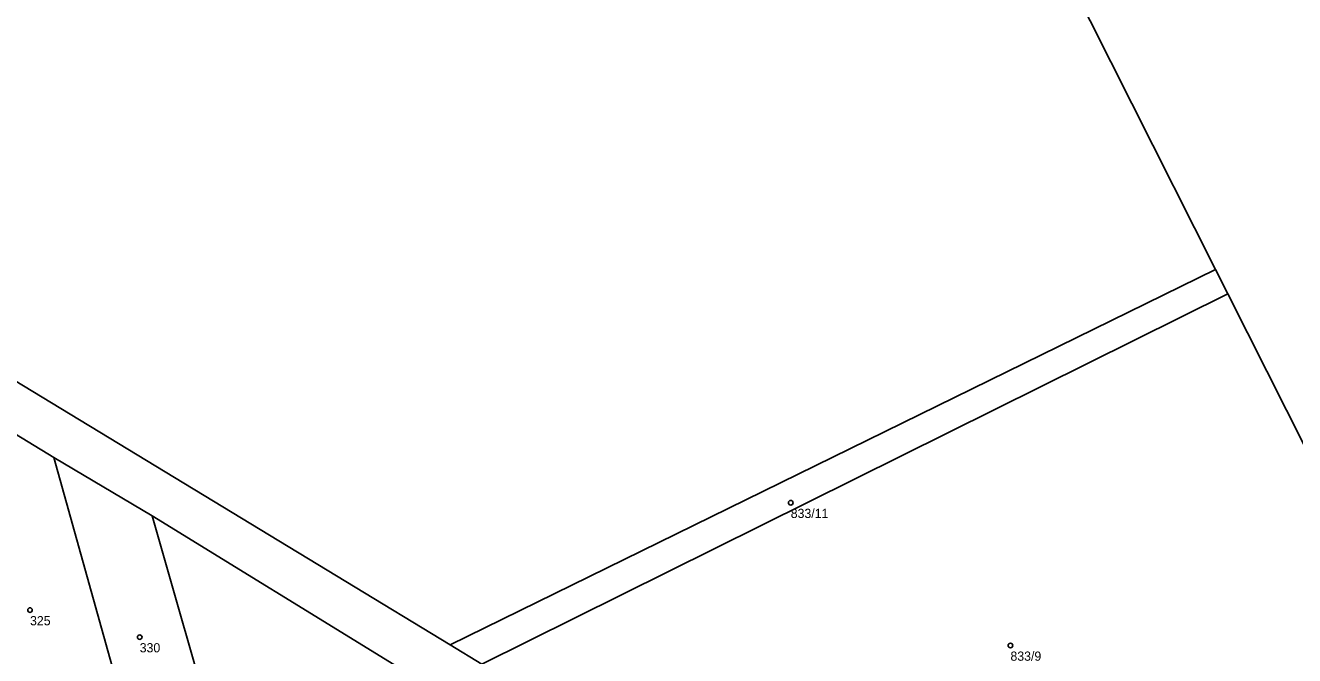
# Model space of a CAD drawing. Extents: x -550098 to -546083, y -1127254 to -1124489.
# Drawn here: x -547295.2 to -547157.4, y -1125565.9 to -1125497.4 of the extents above; entities that cross this region are included whole.
import ezdxf

# ---------------------------------------------------------------- set-up
doc = ezdxf.new("R2010")
doc.units = 0
doc.layers.add('Definiční body', color=7, linetype='Continuous')
doc.layers.add('Polygon parcely', color=7, linetype='Continuous')

msp = doc.modelspace()

# ---------------------------------------------------------------- linework, layer by layer
at = {"layer": 'Definiční body'}
for centre in [(-547212.11, -1125549.23994), (-547294.72, -1125560.89994), (-547282.81, -1125563.83994), (-547188.25, -1125564.74994)]:
    msp.add_circle(centre, 0.25, dxfattribs=at)
at = {"layer": 'Polygon parcely'}
for points in [[(-547165.99, -1125523.88), (-547164.64, -1125526.55), (-547143.41, -1125568.71), (-547117.13, -1125555.75), (-547050.4, -1125523.01), (-547167.11, -1125292.24), (-547252.28, -1125352.54)], [(-547165.99, -1125523.88), (-547252.28, -1125352.54), (-547253.34, -1125353.29), (-547407.05, -1125462.23), (-547406.74, -1125468.91), (-547249.09, -1125564.68)], [(-547245.67, -1125566.76), (-547249.09, -1125564.68), (-547406.74, -1125468.91), (-547411.12, -1125466.23), (-547419.21, -1125474.16), (-547411.31, -1125471.93), (-547407.3, -1125474.3), (-547391.7, -1125483.88), (-547369.07, -1125497.57), (-547353.56, -1125506.98), (-547338.11, -1125516.36), (-547322.81, -1125525.58), (-547307.78, -1125534.79), (-547292.14, -1125544.32), (-547281.45, -1125550.65), (-547255.23, -1125566.81), (-547236.11, -1125578.59), (-547229.52, -1125582.65), (-547223.6, -1125588.68), (-547220.52, -1125599.62), (-547226.05, -1125606.13), (-547227.14, -1125607.42), (-547209.91, -1125601.52), (-547214.02, -1125585.98)], [(-547249.09, -1125564.68), (-547245.67, -1125566.76), (-547164.64, -1125526.55), (-547165.99, -1125523.88)], [(-547245.67, -1125566.76), (-547214.02, -1125585.98), (-547209.91, -1125601.52), (-547203.23, -1125598.22), (-547143.41, -1125568.71), (-547164.64, -1125526.55)], [(-547283.76, -1125574.28), (-547292.14, -1125544.32), (-547307.78, -1125534.79), (-547297.19, -1125572.77)], [(-547292.14, -1125544.32), (-547283.76, -1125574.28), (-547274.38, -1125575.35), (-547281.45, -1125550.65)], [(-547281.45, -1125550.65), (-547274.38, -1125575.35), (-547252.47, -1125577.2), (-547255.23, -1125566.81)]]:
    msp.add_lwpolyline(points, close=True, dxfattribs=at)

# ---------------------------------------------------------------- texts
at = {"layer": 'Definiční body'}
for s, p in [('833/11', (-547212.11, -1125550.896)), ('325', (-547294.72, -1125562.556)), ('330', (-547282.81, -1125565.496)), ('833/9', (-547188.25, -1125566.406))]:
    msp.add_text(s, height=0.999996, dxfattribs=at).set_placement(p)

doc.saveas('drawing.dxf')
